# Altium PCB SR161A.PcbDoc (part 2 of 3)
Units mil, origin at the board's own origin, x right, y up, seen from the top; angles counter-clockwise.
Board outline 3150 x 3740 mil, 6 copper layers (Top Layer, Signal Layer 1, Signal Layer 2, Signal Layer 3, Signal Layer 4, Bottom Layer), stack 61.4 mil thick; 187 components, 70 nets, 452 pads, 384 vias.
Unrouted connection lines stored in the file: 5.
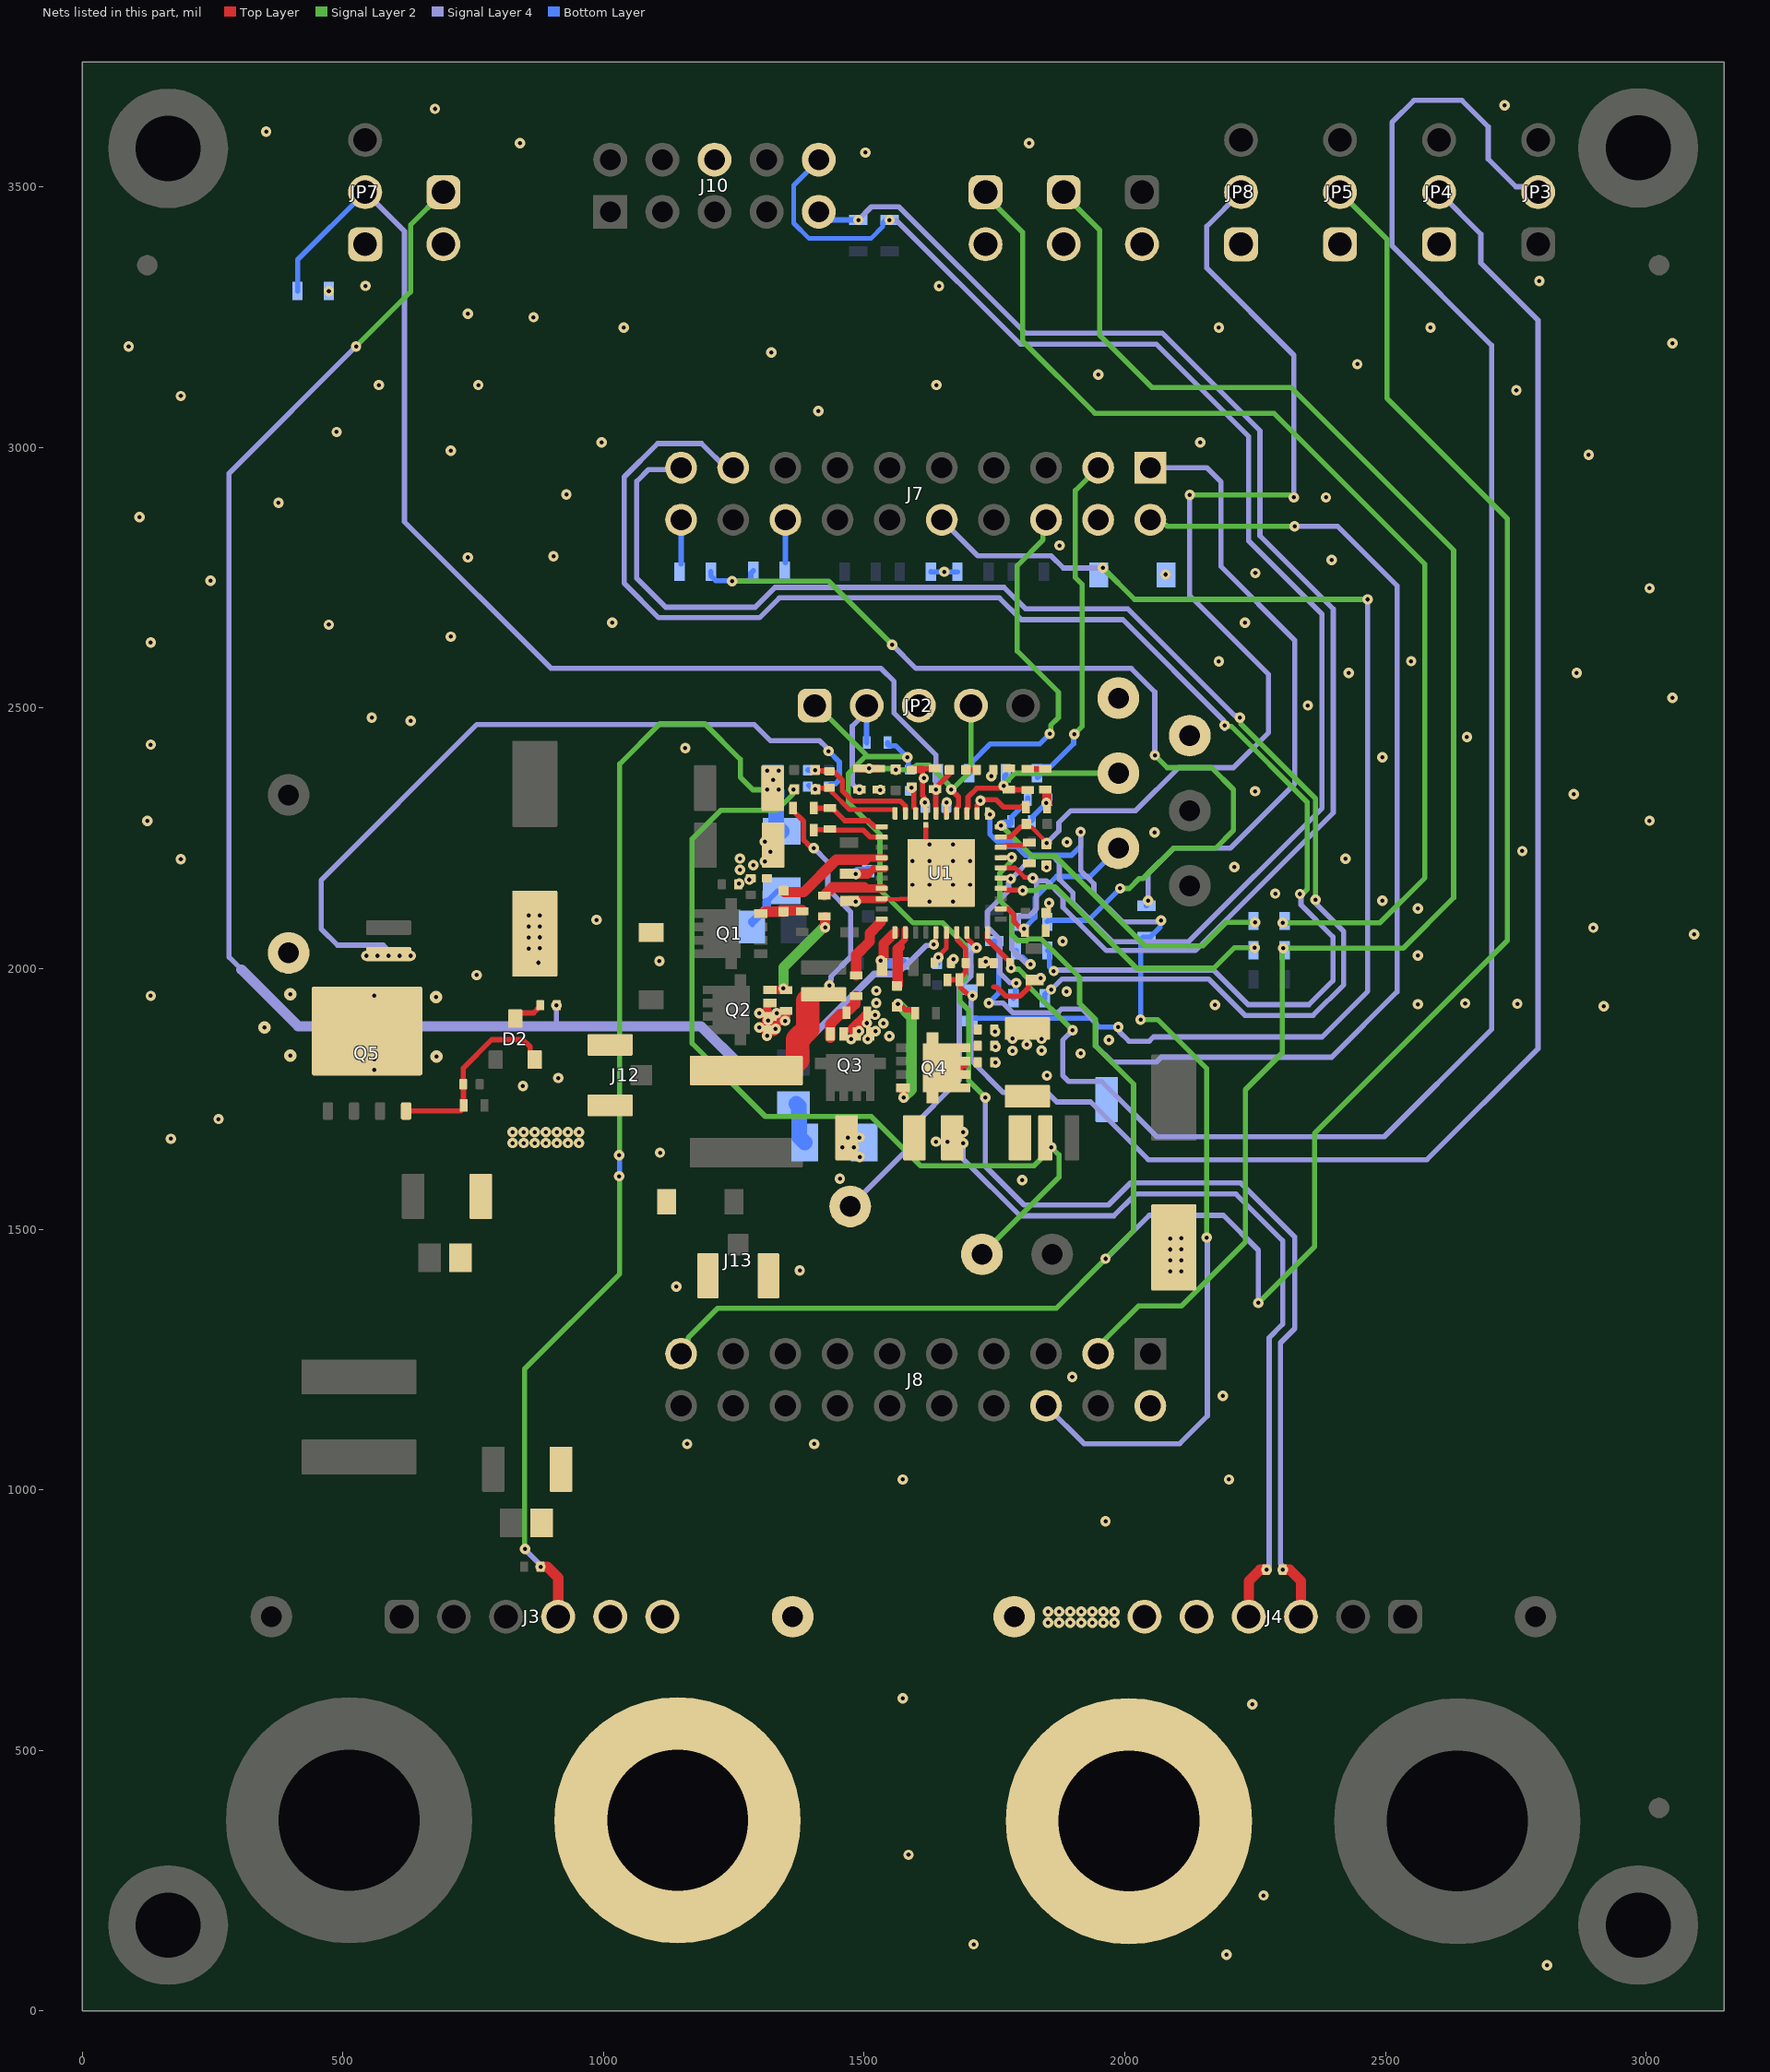
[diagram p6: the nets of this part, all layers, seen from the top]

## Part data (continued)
C35: library part CMP-0006478-2, "CAP, CERM, 56 pF, 50 V, +/- 5%, C0G/NP0, 0402", Cap_Case=0402, Manufacturer=MuRata, Supplier Part Number 1=14T3298, TempCo=C0G/NP0, Tolerance_%=5%, Value1=Unknown, Value2=50V, ValueDisplayed=56pF
C36: library part CMP-0006698-2, "CAP, CERM, 8200 pF, 50 V, +/- 10%, X7R, 0402", Cap_Case=0402, Manufacturer=MuRata, Supplier Part Number 1=GRM155R71H822KA88D-ND, TempCo=X7R, Tolerance_%=10%, Value1=Unknown, Value2=50V, ValueDisplayed=8200pF
C37: library part CMP-0006647-2, "CAP, CERM, 0.022 uF, 16 V, +/- 10%, X7R, 0402", Cap_Case=0402, Manufacturer=MuRata, Supplier Part Number 1=490-3256-1-ND, TempCo=X7R, Tolerance_%=10%, Value1=Unknown, Value2=16V, ValueDisplayed=0.022uF
C43 C45: library part CMP-0008374-2, "CAP, CERM, 0.47 uF, 100 V, +/- 10%, X7R, 0805", Cap_Case=0805, Manufacturer=MuRata, Supplier Part Number 1=490-3326-1-ND, TempCo=X7R, Tolerance_%=10%, Value1=Unknown, Value2=100V, ValueDisplayed=0.47uF
D1: library part CMP-0005781-3, "Diode, Zener, 3.3 V, 500 mW, SOD-123", Manufacturer="ON Semiconductor", Power_W=500mW, Value1=0.5W
D2: library part CMP-0096356-1, "Diode Array 1 Pair Series Connection Schottky 70 V 200mA (DC) Surface Mount TO-236-3, SC-59, SOT-23-3", Digikey Part Number=BAS70-04-E3-18GICT-ND, Forward Current=200mA, Manufacturer=Vishay, Max Surge Forward Current=600mA, Mouser Part Number=78-BAS70-04-E3-18, Operating Temperature Range="-55°C to +125°C", Peak Reverse Current=0.02uA, ValueDisplayed=1.5pF
D3 D6: library part CMP-0079239-2, "Diode, Schottky, 60 V, 1 A, AEC-Q101, SOD-123", Manufacturer=Nexperia, Value1=1A, Value2=0.66V
D4 D5: library part CMP-0077011-2, "Diode, Schottky, 60 V, 1 A, SOD-323F", Manufacturer=Nexperia, Value1=1A, Value2=0.66V
FID1 FID2 FID3 FID4 FID5 FID6: library part CMP-0077181-1, "Fiducial mark.  There is nothing to buy or mount.", Manufacturer=N/A
H1 H2 H3 H4: library part CMP-0003715-1, "MACHINE SCREW PAN PHILLIPS 4-40", Manufacturer="B&F Fastener Supply", Supplier Part Number 1=H703-ND
J1 J2 J5 J6: library part CMP-0055387-2, "Standard Banana Jack, Uninsulated, 15A", Manufacturer="Cinch Connectivity", Supplier Part Number 1=J147-ND
J3 J4: library part CMP-0054801-2, "Header, 2.54 mm, 6x1, Gold, TH", Color=Black, Manufacturer="Wurth Elektronik", Supplier Part Number 1=732-5319-ND
J7 J8: library part CMP-0079854-1, "Receptacle, 2.54mm, 10x2, Tin, TH", Color=Black, Current_A=6.3A, Manufacturer=Samtec, Supplier Part Number 1=SAM1204-10-ND, Voltage_V=550V
J9 J11 JP1 JP6: library part CMP-0054794-2, "Header, 2.54 mm, 2x1, Gold, TH", Color=Black, Manufacturer="Wurth Elektronik", Supplier Part Number 1=732-5315-ND
J10: library part CMP-0055448-2, "Header (shrouded), 100mil, 5x2, High-Temperature, Gold, TH", Manufacturer=3M, Supplier Part Number 1=MHC10K-ND
J12 J13: library part CMP-0124001-1, "U.FL (UMCC), I-PEX MHFI Connector Receptacle, Male Pin 50 Ohms Surface Mount Solder", Dielectric Material="Liquid Crystal Polymer", Digikey Part Number=SAM10680-ND, Frequency_Fixed=6GHz, Manufacturer=Samtec, Operating Temperature Range="-40°C to +90°C", Voltage_V=60V
JP2: library part CMP-0084909-1, "Header, 2.54mm, 5x1, Gold, TH", Color=Black, Current_A=3A, Manufacturer="Wurth Elektronik", Voltage_V=250V
JP3 JP4 JP5 JP7 JP8: library part CMP-0054796-4, "Header, 2.54 mm, 3x1, Gold, TH", Manufacturer="Wurth Elektronik", Supplier Part Number 1=732-5316-ND
L1: library part CMP-0127655-4, "3.3 µH Shielded Molded Inductor 20.4 A 6.5mOhm Max Nonstandard", Digikey Part Number=732-744393465033CT-ND, Manufacturer="Wurth Electronics", Mouser Part Number=710-744393465033, Operating Temperature Range="-55°C to +150°C", Self Resonant Frequency=21MHz, Test Frequency=100kHz, Tolerance_%=20%
L2: library part CMP-0126346-1, "2.2 µH Shielded Molded Inductor 12.4 A 9.3mOhm Max Nonstandard", Digikey Part Number=732-7443845030022CT-ND, Manufacturer="Wurth Electronics", Mouser Part Number=710-7443845030022, Operating Temperature Range="-40°C to +125°C", Self Resonant Frequency=35MHz, Test Frequency=100kHz, Tolerance_%=20%
Logo3: library part CMP-0074847-1, "FCC_disclaimer"
LOGO4: library part CMP-0074769-4, Manufacturer="Texas Instruments"
Logo5: library part CMP-0074837-2, "IEC 61010-1 Hot Surface Warning", Manufacturer="Texas Instruments"
Logo6: library part CMP-0074836-1, "IEC 61010-1 Caution Warning"
MP1 MP2 MP3 MP4: library part CMP-0090542-1, "Hex Standoff Threaded #4-40 Nylon 0.750\" (19.05mm) 3/4\" Natural", Digikey Part Number=36-1902D-ND, Manufacturer="Keystone Electronics", Mouser Part Number=534-1902D, Operating Temperature Range=to
NT3: library part CMP-0078142-6, "Single point connection between nets.", Manufacturer=N/A
Q1 Q2 Q3 Q4: library part CMP-0127418-3, "MOSFET N-Channel 40 V 72A (Tj) 45W (Tc) Surface Mount PG-TSDSON-8-44", Digikey Part Number=448-IAUZN04S7L046ATMA1CT-ND, Drain To Source Breakdown Voltage=40V, Input Capacitance At Vds="810pF @ 20V", Manufacturer=Infineon, Mouser Part Number=726-IAUZN04S7L046ATM, Operating Temperature Range="-55°C to +175°C", Power_W=45W, Pulse Drain Current=165A, Typ Forward Diode Voltage=0.8V
Q5: library part CMP-0000823-2, "MOSFET, N-CH, 60 V, 100 A, DNK0008A (VSON-CLIP-8)", Alternate Manufacturer=None, Manufacturer="Texas Instruments", Supplier Part Number 1=296-41076-1-ND, Value1=0.003, Value2="41 nC"
R1 R3: library part CMP-0097451-1, "10 mOhms ±1% 1W Chip Resistor Wide 0805 (2012 Metric), 0508 Automotive AEC-Q200, Current Sense Metal Foil", Manufacturer=Susumu, Operating Temperature Range="-55°C to +155°C", Power_W=1W, TempCo=50ppm/°C, Tolerance_%=1%
R2 R5 R7 R9 R10 R11 R13 R14 R15 R20 R24 R35 R36 R38 R52: library part CMP-0002710-1, "0 Ohms Jumper Chip Resistor 0402 (1005 Metric) Automotive AEC-Q200 Thick Film", Digikey Part Number=P0.0JCT-ND, Manufacturer=Panasonic, Mouser Part Number=667-ERJ-2GE0R00X, Operating Temperature Range="-55°C to +155°C", Power=100mW
R4: library part CMP-0095678-1, "4 mOhms ±1% 1W Chip Resistor Wide 0805 (2012 Metric), 0508 Automotive AEC-Q200, Current Sense Metal Foil", Digikey Part Number=408-1594-1-ND, Manufacturer=Susumu, Mouser Part Number=754-KRL2012EMR004FT5, Operating Temperature Range="-55°C to +155°C", Power_W=1W, TempCo=50ppm/°C, Tolerance_%=1%
R6 R16 R27 R33 R41 R42 R43 R49 R50 R51 R55: library part CMP-0023343-3, "RES, 0, 1%, 0.1 W, AEC-Q200 Grade 0, 0603", Manufacturer="Stackpole Electronics Inc", Power_W=100mW, Supplier Part Number 1=RMCF0603ZT0R00CT-ND, TempCo=ppm/C, Tolerance_%=1%, Value2=0.1W, Value_Code=0
R8 R17 R18: library part CMP-0025963-3, "RES, 10.0, 1%, 0.063 W, AEC-Q200 Grade 0, 0402", Manufacturer=Vishay-Dale, Power_W=63mW, Supplier Part Number 1=541-10.0LCT-ND, TempCo="100 ppm/C", Tolerance_%=1%, Value2=0.063W, Value_Code=10R0, ValueDisplayed=10.0
R12: library part CMP-0026744-1, "RES, 82.0 k, 1%, 0.063 W, 0402", Manufacturer="Yageo America", Power_W=63mW, Supplier Part Number 1=311-82.0KLRCT-ND, TempCo="100 ppm/C", Tolerance_%=1%, Value2=0.063W, Value_Code=82k0, ValueDisplayed=82.0k
R19: library part CMP-0026240-2, "RES, 2.67 k, 1%, 0.063 W, AEC-Q200 Grade 0, 0402", Manufacturer=Vishay-Dale, Power_W=63mW, Supplier Part Number 1=541-2.67KLCT-ND, TempCo="100 ppm/C", Tolerance_%=1%, Value2=0.063W, Value_Code=2k67, ValueDisplayed=2.67k
R21: library part CMP-0026543-2, "RES, 75.0 k, 1%, 0.063 W, AEC-Q200 Grade 0, 0402", Manufacturer=Vishay-Dale, Power_W=63mW, Supplier Part Number 1=541-75.0KLCT-ND, TempCo="100 ppm/C", Tolerance_%=1%, Value2=0.063W, Value_Code=75k0, ValueDisplayed=75.0k
R22: library part CMP-0025993-3, "RES, 12.7 k, 1%, 0.063 W, AEC-Q200 Grade 0, 0402", Manufacturer=Vishay-Dale, Power_W=63mW, Supplier Part Number 1=541-12.7KLCT-ND, TempCo="100 ppm/C", Tolerance_%=1%, Value2=0.063W, Value_Code=12k7, ValueDisplayed=12.7k
R23 R26: library part CMP-0018676-3, "RES, 3.0, 5%, 0.25 W, AEC-Q200 Grade 0, 1206", Manufacturer=Vishay-Dale, Power_W=250mW, Supplier Part Number 1=541-3.0ECT-ND, TempCo="200 ppm/C", Tolerance_%=5%, Value2=0.25W, Value_Code=3R00, ValueDisplayed=3.0
R25: library part CMP-0077124-1, "RES, 10.0 k, 0.1%, 0.1 W, AEC-Q200 Grade 0, 0402", Manufacturer=Vishay/Beyschlag, Power_W=100mW, Supplier Part Number 1=MCS0402-10.0K-MBCT-ND, TempCo="25 ppm/C", Tolerance_%=0.1%, Value2=0.1W, Value_Code=10k0, ValueDisplayed=10.0k
R28 R32: library part CMP-0026925-3, "RES, 3.0, 5%, 0.063 W, AEC-Q200 Grade 0, 0402", Manufacturer=Vishay-Dale, Power_W=63mW, Supplier Part Number 1=541-3.0JCT-ND, TempCo="200 ppm/C", Tolerance_%=5%, Value2=0.063W, Value_Code=3R00, ValueDisplayed=3.0
R29: library part CMP-0026591-2, "RES, 8.66 k, 1%, 0.063 W, AEC-Q200 Grade 0, 0402", Manufacturer=Vishay-Dale, Power_W=63mW, Supplier Part Number 1=541-8.66KLCT-ND, TempCo="100 ppm/C", Tolerance_%=1%, Value2=0.063W, Value_Code=8k66, ValueDisplayed=8.66k
R30: library part CMP-0026367-2, "RES, 40.2 k, 1%, 0.063 W, AEC-Q200 Grade 0, 0402", Manufacturer=Vishay-Dale, Power_W=63mW, Supplier Part Number 1=541-40.2KLCT-ND, TempCo="100 ppm/C", Tolerance_%=1%, Value2=0.063W, Value_Code=40k2, ValueDisplayed=40.2k
R31: library part CMP-0026028-3, "RES, 15.4 k, 1%, 0.063 W, AEC-Q200 Grade 0, 0402", Manufacturer=Vishay-Dale, Power_W=63mW, Supplier Part Number 1=541-15.4KLCT-ND, TempCo="100 ppm/C", Tolerance_%=1%, Value2=0.063W, Value_Code=15k4, ValueDisplayed=15.4k
R34: library part CMP-0026463-2, "RES, 5.11 k, 1%, 0.063 W, AEC-Q200 Grade 0, 0402", Manufacturer=Vishay-Dale, Power_W=63mW, Supplier Part Number 1=541-5.11KLCT-ND, TempCo="100 ppm/C", Tolerance_%=1%, Value2=0.063W, Value_Code=5k11, ValueDisplayed=5.11k
R37: library part CMP-0026241-2, "RES, 2.74 k, 1%, 0.063 W, AEC-Q200 Grade 0, 0402", Manufacturer=Vishay-Dale, Power_W=63mW, Supplier Part Number 1=541-2.74KLCT-ND, TempCo="100 ppm/C", Tolerance_%=1%, Value2=0.063W, Value_Code=2k74, ValueDisplayed=2.74k
R39 R40 R44: library part CMP-0023000-5, "RES, 2.00 k, 1%, 0.1 W, 0603", Manufacturer=Yageo, Power_W=100mW, Supplier Part Number 1=311-2.00KHRCT-ND, TempCo="100 ppm/C", Tolerance_%=1%, Value2=0.1W, Value_Code=2k00, ValueDisplayed=2.00k
R45 R46: library part CMP-0023259-5, "RES, 71.5 k, 1%, 0.1 W, 0603", Manufacturer=Yageo, Power_W=100mW, Supplier Part Number 1=311-71.5KHRCT-ND, TempCo="100 ppm/C", Tolerance_%=1%, Value2=0.1W, Value_Code=71k5, ValueDisplayed=71.5k
R47 R48: library part CMP-0023153-5, "RES, 4.70 k, 1%, 0.1 W, 0603", Manufacturer=Yageo, Power_W=100mW, Supplier Part Number 1=311-4.70KHRCT-ND, TempCo="100 ppm/C", Tolerance_%=1%, Value2=0.1W, Value_Code=4k70, ValueDisplayed=4.70k
R53: library part CMP-0022852-5, "RES, 18.0 k, 1%, 0.1 W, 0603", Manufacturer=Yageo, Power_W=100mW, Supplier Part Number 1=311-18.0KHRCT-ND, TempCo="100 ppm/C", Tolerance_%=1%, Value2=0.1W, Value_Code=18k0, ValueDisplayed=18.0k
R54: library part CMP-0023653-3, "RES, 10.0 k, 0.1%, 0.1 W, 0603", Manufacturer="Yageo America", Power_W=100mW, TempCo="25 ppm/C", Tolerance_%=0.1%, Value2=0.1W, Value_Code=10k0, ValueDisplayed=10.0k
SH-JP1 SH-JP2 SH-JP3 SH-JP4 SH-JP5 SH-JP6 SH-JP7 SH-JP8: library part CMP-0078738-1, "Single Operation 2.54mm Pitch Open Top Jumper Socket", Manufacturer=Harwin, Supplier Part Number 1=952-2881-ND
TP1 TP2 TP5 TP6: library part CMP-0055140-2, "Test Point, Miniature, Orange, TH", Color=Orange, Manufacturer="Keystone Electronics", Supplier Part Number 1=36-5003-ND
TP3 TP14: library part CMP-0055137-2, "Test Point, Miniature, Red, TH", Color=Red, Manufacturer="Keystone Electronics", Supplier Part Number 1=36-5000-ND
TP4 TP7 TP8 TP15: library part CMP-0055138-2, "Test Point, Miniature, Black, TH", Color=Black, Manufacturer="Keystone Electronics", Supplier Part Number 1=36-5001-ND
TP9 TP10 TP11 TP12 TP13: library part CMP-0055141-2, "Test Point, Miniature, Yellow, TH", Color=Yellow, Manufacturer="Keystone Electronics", Supplier Part Number 1=36-5004-ND
U1: library part CMP-0127273-1, "36V VIN4 Switch Buck-Boost Controller with I2C", Manufacturer="Texas Instruments", Max Supply Voltage=36V, Min Supply Voltage=3.5V, Nominal Supply Current=65uA, Operating Temperature Range="-40°C to +150°C", Switching Frequency=100-2200kHz
ZZ2: library part CMP-0077236-1
ZZ3: library part CMP-0077237-1
ZZ4: library part CMP-0077238-1
ZZ5 ZZ6 ZZ7 ZZ8 ZZ9 ZZ10 ZZ11: library part CMP-0077238-1, "These assemblies must comply with workmanship standards IPC-A-610 Class 2, unless otherwise specified."

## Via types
v1: diameter 20, hole 8, Top Layer to Bottom Layer, tented both sides, 366 vias
v2: diameter 19.68, hole 7.87, Top Layer to Bottom Layer, tented both sides, 12 vias
v3: diameter 24, hole 8, Top Layer to Bottom Layer, tented both sides, 6 vias

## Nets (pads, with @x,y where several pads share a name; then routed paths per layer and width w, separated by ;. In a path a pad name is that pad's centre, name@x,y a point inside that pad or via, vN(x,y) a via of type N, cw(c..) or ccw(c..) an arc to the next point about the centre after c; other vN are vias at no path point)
3V3: J7.1 R54.2 | length 1200.7
  Signal Layer 4 w10: v1(2044.9,2130.65) 2044.9,2182.7 2093.48,2231.28 2202.29,2231.28 2326.15,2355.15 2326.15,2630.29 2184.7,2771.74 2184.7,2934 2157.28,2961.43 J7.1@2049.03,2961.43
  Bottom Layer w10: R54.2@2041.62,2120.99 2041.62,2121.2 2041.04,2121.78 2041.39,2122.14 2041.39,2127.15 v1(2044.9,2130.65)
5V0: J7.2 R49.2 | length 2354.3
  Signal Layer 2 w10: J7.2@2049.03,2861.43 2058.8,2851.66 2078.69,2851.66 2081.65,2848.7 v1(2325.79,2848.7)
  Signal Layer 4 w10: v1(1739.25,1934.23) 1766.66,1934.23 1785.27,1915.62 1871.43,1915.62 1878.26,1922.45 1918.6,1922.45 1944.32,1896.73 1944.32,1852.62 1975.7,1821.23 2061.2,1821.23 2070.19,1830.22 2396.78,1830.22 2522.2,1955.63 2522.2,2735.1 2408.59,2848.7 v1(2325.79,2848.7)
  Bottom Layer w10: v1(1739.25,1934.23) 1757.96,1952.93 1757.96,2048.15 1752.57,2053.54 R49.2@1749.42,2053.54
ADDR: JP8.2 R36.2 R38.1 U1.9 | length 2043.5
  Top Layer w8: R36.2@1811.28,2271.06 1821.87,2271.06 1843.62,2249.3 1843.62,2244.14 1844.47,2243.29 1848.53,2243.29 R38.1@1848.53,2239.23
  Top Layer w10: U1.9@1762.17,2252.65 1768.91,2252.65 1768.98,2252.73 1780.82,2252.73 1800.16,2272.06 R36.2@1812.32,2272.06 ; R38.1@1848.53,2239.23 1850.14,2239.23 R38.1@1850.14,2236.56
  Signal Layer 2 w10: v1(2124.72,2909.37) 2316.73,2909.37 2321.73,2904.37 v1(2324.44,2904.37)
  Signal Layer 4 w10: v1(1850.6,2241.56) 1873.73,2264.74 1873.73,2280.39 1896.63,2303.28 2021.03,2303.28 2103.54,2385.79 2208.58,2385.79 2275.85,2453.05 2275.85,2564.69 2124.72,2715.82 v1(2124.72,2909.37) ; JP8.2@2223,3490.37 2157.28,3424.65 2157.28,3344.26 2324.44,3177.1 v1(2324.44,2904.37)
AGND: C14.2 C15.1 C16.2 C18.2 C26.1 C28.1 C29.2 C34.2 C35.2 C36.2 C37.2 D1.2 J9.2 J10.6 J11.2 JP1.2 JP2.3 JP4.1 JP5.1 JP6.2 JP7.1 JP8.1 NT3.2 R10.1 R19.1 R22.1 R24.2 R30.1 R31.1 R37.1 R38.2 R47.1 R48.1 R53.1 TP4.1 TP7.1 U1.17 | length 379.4
  Top Layer w10: C16.2@1591.32,2381.25 C16.2@1592.05,2381.98 ; 1611.78,2381.98 1612.51,2382.71 ; v1@1616.4,2319.5 1614.48,2321.41 1614.48,2329.97 1612.51,2331.95 1612.51,2365.61 1612.51,2382.71 ; v1@1618.39,2316.21 1618.39,2303.83 1618.47,2303.76 U1.17@1618.47,2297.93 ; C14.2@1635.97,2384.45 1635.11,2383.58 1613.38,2383.58 1612.51,2382.71 ; C29.2@1724.64,2009.23 1725.08,2009.66 1733.24,2009.66 v1(1733.24,2013.72) C29.2@1733.3,2013.78 ; C28.1@1748.82,2013.78 C28.1@1748.87,2013.83 ; 1749,1965.18 1753.03,1965.18 1754.86,1963.35 1756.02,1963.35 1771.82,1947.55 1799.37,1947.55 1814.66,1962.84 1814.66,1973.7 1822.74,1981.77 C26.1@1838.46,1981.77
  Top Layer w14: C16.2@1592.05,2381.98 1611.78,2381.98
  Top Layer w18: C36.2@1850.6,2341.95 1850.6,2320.47 R31.1@1852.32,2318.75
  Bottom Layer w10: R48.1@1628.34,2761.76 1628.45,2761.65 R47.1@1678.93,2761.65 ; C35.2@1822.02,2285.09 1823.72,2286.8 1823.72,2292.18 v1(1849.63,2318.09) ; R30.1@1850.91,2318.86 R30.1@1851.64,2318.13
  other v1: 2810,88.08 2194.94,108.08 1573.91,600 1573.91,1020 2188.02,1180.43 1899.26,1216.68 1139.75,1390.05 1803.18,1594.72 261.74,1711.72 845.65,1775 1850.76,1794.99 1915.27,1837.45 1969.54,1863.66 2919.05,1928.02 2173,1930.68 2562.06,1931.92 2753,1932.86 2653,1933.62 1888.55,1956.44 1838.51,1982.02 1671.33,2018.06 2562.56,2025.37 1880.81,2052.64 3092.45,2066.21 2898.81,2078.71 2562.06,2115.59 1855.01,2126.43 2494.04,2130.62 2288.59,2144.22 1849.78,2194.71 2210.16,2195.24 2423.39,2211.07 2762.58,2225.79 1889.33,2243.24 2057.36,2261.62 125,2283.54 3006.79,2283.98 1616.22,2318.96 2861.33,2334.81 2250.22,2340.6 1531.16,2343.24 1614.51,2365.61 1743.97,2369.34 2494.04,2405.59 1156.96,2423.68 2656.45,2444.77 630.48,2475.53 2351.24,2505.1 3050.51,2520 2429.4,2567.39 2866.95,2567.39 2180.52,2590 2549.43,2590.12 131.66,2625.86 707.24,2637.18 473.23,2660.18 1016.71,2664.16 2230.82,2664.18 3006.79,2730 246.43,2744.78 2078.37,2756.51 2250.46,2759.19 1653.69,2761.65 2396.78,2784.25 740,2789.26 904.19,2791.35 1874.71,2812.21 110,2866.76 376.79,2893.84 2385.99,2904.37 928.95,2910 2890,2986.3 707.24,2993.84 996.6,3010 2144.72,3010 488.21,3030 1412.06,3070 189.28,3098.97 2751.2,3110 569.08,3120 760,3120 1638.99,3120 1949.03,3140 2446.1,3160 1322.17,3182.55 89.29,3193.88 3050.51,3200 1039.08,3230 2180.52,3230 2586.6,3230 865.96,3250 740,3256.68 473.23,3300 543.61,3310.24 1643.7,3309.63 2795.25,3319.69 1502.51,3566.01 840,3583.84 1816.62,3583.84 353,3606.4 676.76,3650 2728.43,3656.8
BIAS: C28.2 JP3.2 U1.40 | length 3525.9
  Top Layer w10: U1.40@1736.58,2069.58 1736.58,2056.35 1777.26,2015.67 1777.49,2015.67 1778.49,2014.68 C28.2@1778.49,2014.45
  Signal Layer 2 w10: v1(1781.76,2001.17) 1783.68,1999.25 1796.54,1999.25 1814.55,1981.24 1814.55,1967.41 v1(1899.99,1881.97)
  Signal Layer 4 w10: v1(1899.99,1881.97) 1880.88,1862.86 1880.88,1795.3 1892.63,1783.55 1955.91,1783.55 2061.78,1677.68 2497.68,1677.68 2703.62,1883.62 2703.62,3196.38 2512.78,3387.22 2512.78,3624.05 2554.81,3666.07 2646.7,3666.07 2697.13,3615.64 2697.13,3553.62 2750.24,3500.52 2782.85,3500.52 JP3.2@2793,3490.37
CDC: C35.1 R30.2 R50.1 U1.10 | length 688.2
  Top Layer w10: U1.10@1762.17,2272.34 1768,2272.34 1768.08,2272.42 U1.10@1768.08,2276.26
  Signal Layer 2 w10: v1@1763.44,2274.65 1822.39,2215.71 1866.94,2215.71 2038.75,2043.89 2149.79,2043.89 2194.91,2089.01 v1(2250.16,2089.01)
  Bottom Layer w10: v1(1762.9,2274.65) 1765.61,2274.65 v1@1769.9,2278.94 ; C35.1@1779.52,2278.94 1782.02,2281.44 C35.1@1782.02,2285.09 ; C35.1@1782.02,2290.44 1783.66,2290.44 1783.72,2290.5 1783.72,2292.15 1811.1,2319.53 1811.51,2319.53 1813.99,2322.01 R30.2@1813.99,2327.9
  Bottom Layer w15: v1@1769.9,2278.94 C35.1@1779.52,2278.94
CDCP: J11.1 R50.2 | length 2172.3
  Signal Layer 2 w10: J11.1@1730.52,3486.8 1803.91,3413.41 1803.91,3204.54 1942.55,3065.89 2286.11,3065.89 2575.79,2776.21 2575.79,2174.35 2489.85,2088.41 v1(2302.86,2088.41)
CFG2: R37.2 U1.8 | length 51.7
  Top Layer w10: U1.8@1768.98,2233.05 1772.67,2236.73 1807.28,2236.73 1812.5,2241.96 R37.2@1817,2241.96
COMP: C34.1 R16.2 R29.2 TP12.1 U1.13 | length 410.1
  Top Layer w10: U1.13@1697.21,2297.93 1697.21,2306.55 1699.42,2308.76 1699.42,2329.67 1715.95,2346.2 1760.38,2346.2 1764.92,2350.74 v1(1767.62,2350.74) 1767.62,2349.94 1773.44,2344.12 C34.1@1777.94,2344.12 ; C34.1@1782.49,2343.28 R29.2@1813.66,2343.28
  Signal Layer 2 w10: v1(1767.62,2350.74) 1767.62,2353.44 1782.21,2368.03 1782.21,2368.21 1789.28,2375.28 TP12.1@1987.84,2375.28
  Bottom Layer w10: v1(1767.62,2350.74) 1769.54,2352.65 1769.54,2369.49 R16.2@1772.51,2372.46
CSA/SW1: C25.2 R17.1 U1.22 | length 139.4
  Top Layer w10: R17.1@1403.57,2260.5 1410.09,2267.03 C25.2@1434.66,2267.03 ; C25.2@1434.64,2268.19 1436.96,2265.87 1498.63,2265.87 1511.85,2252.65 U1.22@1533.83,2252.65
CSB: C25.1 R18.1 U1.21 | length 137.4
  Top Layer w10: R18.1@1403.53,2307.9 C25.1@1434.35,2307.9 ; C25.1@1441.39,2305.94 1441.64,2305.69 1441.64,2305.25 1462.89,2284 1508.48,2284 1520.14,2272.34 U1.21@1533.83,2272.34
DRV1: C6.1 J9.1 U1.35 | length 3237.2
  Top Layer w9: v1(1633.81,2046.6) 1633.81,2049.58 1637.74,2053.5 1637.74,2069.16 U1.35@1638.16,2069.58
  Signal Layer 2 w10: v1@525.54,3194.25 630,3298.71 630,3427.37 J9.1@693,3490.37
  Signal Layer 4 w10: 305.81,1998.43 281.93,2022.31 281.93,2950.64 v1@525.54,3194.25 ; 909.19,1889.65 909.85,1890.3 v1(909.85,1929.76) ; 1564.27,1989.85 1619.31,2044.9 1632.11,2044.9 v1(1633.81,2046.6)
  Signal Layer 4 w13: 1344.36,1814.95 1519.26,1989.85 1564.27,1989.85
  Signal Layer 4 w20: 305.81,1998.43 414.6,1889.65 909.19,1889.65 1187.21,1889.65 1261.9,1814.95 1344.36,1814.95
  other v1: 525.54,3193.88
DTRK: R51.1 U1.4 | length 565.6
  Top Layer w10: U1.4@1768.98,2154.15 1771.89,2151.24 1803.67,2151.24 v1(1804.57,2150.34)
  Signal Layer 2 w10: v1(1804.57,2150.34) 1831.03,2150.34 1838,2157.31 1866.62,2157.31 2022.78,2001.14 2171,2001.14 2210.06,2040.2 v1(2249.26,2040.2)
DTRKP: J8.3 JP1.1 R51.2 | length 3158.2
  Signal Layer 2 w10: JP1.1@1882.18,3486.8 1951.87,3417.11 1951.87,3215.52 2051.99,3115.39 2318.61,3115.39 2630.78,2803.22 2630.78,2136.12 2534.26,2039.6 v1(2304.06,2039.6) 2302.34,2037.88 2302.34,1838.7 2231.56,1767.92 2231.56,1475.79 2108.85,1353.09 2026.37,1353.09 1964.05,1290.77 1964.05,1290.25 1949.03,1275.23 J8.3@1949.03,1260.42
EN/UVLO: C29.1 JP4.2 R21.1 R22.2 R44.1 U1.37 | length 3251.2
  Top Layer w9: U1.37@1677.53,2069.58 1677.95,2069.16 1677.95,2055.71 1695.06,2038.6 C29.1@1695.06,2011.25
  Top Layer w10: R21.1@1660.03,1978.74 1660.14,1978.86 1680.49,1978.86 1680.6,1978.97 R22.2@1682.99,1978.97 ; R22.2@1685.49,1979.47 1685.49,1964.03 1696.67,1952.85 ; R22.2@1687.54,1986.55 1694.76,1993.77 C29.1@1694.76,2013.59
  Signal Layer 4 w10: v1(1708.08,1948.19) 1706.17,1946.27 1706.17,1939.2 1705.25,1938.29 1705.25,1824.09 1766.64,1762.69 1851.42,1762.69 1869.73,1744.39 1934.52,1744.39 2045.29,1633.62 2579.53,1633.62 2792.69,1846.77 2792.69,3244.35 2683,3354.04 2683,3409.56 JP4.2@2603,3489.56
EN/UVLOP: D1.1 J7.10 R44.2 | length 2452
  Signal Layer 2 w10: v1(1957.98,2769.35) 2018.61,2708.72 v1(2466.1,2708.72)
  Signal Layer 4 w10: J7.10@1649.03,2861.43 1649.03,2849.95 1660.51,2849.95 1718.08,2792.38 1858.78,2792.38 1882.21,2768.95 v1@1950.55,2768.95 ; v1@1989.75,1879.42 2008.1,1861.08 2046.96,1861.08 2055.12,1869.24 2378.59,1869.24 2466.1,1956.75 v1(2466.1,2708.72)
  Bottom Layer w10: R44.2@1700,1900 1705,1905 1934.86,1905 1951.78,1888.08 v1(1987.57,1888.08)
FB: JP2.4 R2.1 R12.1 R19.2 U1.14 | length 450.5
  Top Layer w10: v1(1666.83,2344.04) 1681.12,2329.75 1681.12,2311.61 1677.54,2308.03 U1.14@1677.53,2297.93
  Top Layer w15: R12.1@1491.02,2384.12 v1(1509.69,2384.11) ; v1(1509.69,2384.11) R19.2@1528.4,2384.07
  Signal Layer 2 w10: v1@1510.89,2384.06 v1@1560.86,2384.06 ; v1@1560.78,2383.24 1560.86,2383.17 v1(1560.86,2381.68) ; v1@1562.34,2381.68 1592.35,2381.68 1601.14,2390.48 1624.91,2390.48 1661.83,2353.55 1661.83,2351.75 1666.83,2346.75 v1(1666.83,2344.04) 1669.14,2344.04 1705,2379.91 JP2.4@1705,2505
GND: C1.1 C3.1 C5.1 C7.1 C8.1 C9.1 C10.1 C11.2 C12.2 C13.1 C17.1 C19.1 C20.1 C21.1 C23.2 C24.1 C27.1 C39.2 C40.1 C41.2 C42.2 C43.2 C44.1 C45.2 D3.2 D6.2 J3.4 J3.5 J3.6 J4.4 J4.5 J4.6 J5.1 J6.1 J7.4 J8.2 J12.2 J12.3 J13.2 J13.3 NT3.1 Q2.1 Q2.2 Q2.3 Q3.1 Q3.2 Q3.3 R23.2 R26.2 TP8.1 TP15.1 U1.28 U1.41 | length 4140.4
  Top Layer w9: U1.28@1536.96,2133.1 U1.41@1598.5,2134.26
  Top Layer w10: Q2.2@1316.89,1911.11 Q2.3@1316.89,1930.47 ; NT3.1@1618.3,2274.71 1618.3,2243.72 1623.14,2238.87 v2(1625.36,2238.87)
  Top Layer w14: C27.1@1471.87,2130.07 1474.9,2133.1 1536.96,2133.1 U1.28@1538.59,2133.1
  Top Layer w20: v1(879.42,852.61) 892.13,852.61 913.61,831.13 J3.4@913.61,756.82 ; v1@1313.58,1871.61 1313.58,1918.86 ; Q2.1@1317.97,1882.81 Q2.1@1319.23,1882.81 ; Q2.2@1319.23,1908.4 1320.38,1909.54 1344.87,1909.54 ; v1(1330.42,1884.65) 1326.88,1881.1 1320.94,1881.1 Q2.1@1319.23,1882.81 ; 1333.56,1897.13 Q2.1@1319.23,1882.81 ; C27.1@1471.87,2130.07 C27.1@1478.3,2130.07 ; 1477.66,1883.92 C23.2@1503.66,1909.93 ; J4.4@2238,751.05 J4.4@2238,756.82 2238,825.37 2259.48,846.85 v1(2272.19,846.85) ; 1344.87,1909.54 1348.84,1909.54 1348.84,1913.51 1344.87,1909.54
  Signal Layer 2 w10: v1(849.71,886.98) 848.82,887.87 848.82,1232.28 1031.24,1414.7 v1@1031.24,1601.97 ; v1@1031.24,1642.19 1031.24,2393.07 1107.97,2469.8 1194.75,2469.8 1262.53,2402.01 1262.53,2367.69 1286.73,2343.49 v1(1314.45,2343.49)
  Signal Layer 4 w10: v1(849.71,886.98) 849.71,885.25 874.42,860.54 874.42,860.32 879.42,855.32 v1(879.42,852.61) ; v1@1691.53,1664.26 1690.13,1662.86 1690.13,1634.9 1799.13,1525.9 1979.07,1525.9 2021.02,1567.85 2213.21,1567.85 2302.86,1478.2 2302.86,1317.96 2277,1292.1 2277,854.36 2272.19,849.55 v1(2272.19,846.85)
  Bottom Layer w10: v1@1031.24,1601.97 v1@1031.24,1642.19 ; v1(1638.05,1668.23) v1(1659.63,1668.23) 1684.36,1668.23 1687.42,1665.17 v1(1690.13,1665.17)
  Bottom Layer w30: C19.1@1325.01,2333.95 1331.66,2327.3 1331.66,2273.96 R23.2@1342.15,2263.48 ; C19.1@1325.01,2347.5 1331.9,2340.61 C19.1@1331.9,2332.03
  other v1: 1710,128.08 2266.27,221.92 1585.24,300 2244.6,588.67 1852.59,745.52 1873.86,745.52 1895.12,745.52 1916.38,745.52 1937.65,745.52 1958.91,745.52 1980.17,745.52 1852.59,766.63 1873.86,766.63 1895.12,766.63 1916.38,766.63 1937.65,766.63 1958.91,766.63 1980.17,766.63 1963.04,940 2199.9,1020 1160.58,1088.18 1404.32,1088.18 2087.13,1419.03 2108.14,1419.73 1376.56,1421.4 2087.13,1440.22 2108.14,1440.92 2087.13,1461.41 2108.14,1462.12 2087.13,1482.6 2108.14,1483.31 1453.54,1596.97 1030,1601.97 1491.62,1638.78 1030,1642.19 1108.52,1647.02 1458.02,1657.54 1480.35,1657.54 825.65,1665.64 846.91,1665.64 868.17,1665.64 889.44,1665.64 910.7,1665.64 931.97,1665.64 953.23,1665.64 170,1673.81 1469.08,1676.3 1491.41,1676.3 825.65,1686.75 846.91,1686.75 868.17,1686.75 889.44,1686.75 910.7,1686.75 931.97,1686.75 953.23,1686.75 1690.13,1686.75 913.17,1790.44 1751.91,1819.75 1784.56,1842.64 1840.28,1843.17 1752.4,1850 1812.4,1854.42 1475.02,1864.97 1507.07,1864.97 1784.56,1866.23 1840.45,1865.54 1313.78,1871.12 1548.77,1870.51 1490.31,1880.36 1522.15,1880.05 1751.39,1879.52 1299.1,1887.48 1537.2,1895.48 1505.59,1895.76 1348.84,1900.1 1315.74,1901.01 1521.26,1911.66 1299.1,1914.54 1332.38,1914.54 1523.44,1934.23 131.66,1948.04 1523.44,1957.75 756.55,1987.93 874.89,2011.65 1107.45,2014.68 856.89,2038.41 877.9,2039.12 856.89,2059.61 877.9,2060.31 856.89,2080.8 877.9,2081.51 986.85,2093.78 856.89,2101.99 877.9,2102.7 1484.07,2128.88 1260.5,2163.16 1279.9,2170.9 1261.91,2189.64 1287.59,2198.68 1309.3,2206.18 189.28,2210 1262.11,2211.45 1320.24,2224.79 1309.6,2244.09 1336.26,2343.49 1325.55,2362.04 1314.21,2379.68 1336.02,2379.68 131.66,2430 555.54,2481.91
  other v2: 1625.36,2128.64 1670.64,2128.64 1592.88,2161.12 1625.36,2161.12 1670.64,2161.12 1703.12,2161.12 1592.88,2206.39 1625.36,2206.39 1670.64,2206.39 1703.12,2206.39 1670.64,2238.87
HB1: C31.2 D4.1 U1.25 | length 80.3
  Top Layer w14: 1511.11,2185.17 1517.78,2191.83 U1.25@1539.78,2191.83
  Top Layer w20: C31.2@1482.8,2182.42 1506.13,2182.42
  Bottom Layer w20: v1(1484.31,2182.14) 1487.57,2185.4 1505.9,2185.4 D4.1@1507.71,2187.21
HB2: C33.2 D5.1 U1.31 | length 117.4
  Top Layer w12: U1.31@1560.28,2063.52 U1.31@1560.28,2075.52
  Top Layer w20: C33.2@1531.87,2015.39 1537.44,2020.96 1537.44,2047.6 U1.31@1556.34,2066.5
  Bottom Layer w20: v1(1532.12,2015.64) 1537.64,2010.13 D5.1@1573.96,2010.13
HO1: R13.2 U1.24 | length 216
  Top Layer w10: U1.24@1533.75,2213.36 U1.24@1533.83,2213.28
  Top Layer w14: 1504.57,2212.17 U1.24@1539.57,2212.17
  Top Layer w20: R13.2@1347.59,2147.16 1356.98,2147.16 1384.55,2147.15 1446.7,2209.31 1502.73,2209.31
HO1_G: C38.1 Q1.4 R13.1 | length 82.7
  Top Layer w20: Q1.4@1304.69,2106.87 1307.96,2106.87 1310.75,2109.66 R13.1@1345.59,2109.66 ; R13.1@1340.53,2112.23 C38.1@1381.16,2112.23
HO2: R20.2 U1.32 | length 113
  Top Layer w12: 1568.38,2041.77 1568.38,2045.99 1576.34,2053.95 1576.34,2054.24 1578.34,2056.24 U1.32@1578.34,2075.74
  Top Layer w20: R20.2@1564.3,1968.52 1564.3,2037.69 1568.38,2041.77
HO2_G: C22.2 Q4.4 R20.1 | length 255.9
  Top Layer w10: v1(1564.88,1932.76) 1567.58,1932.76 1571.44,1928.91 1578.8,1921.54 1592.55,1921.54 1595.05,1919.04 C22.2@1595.05,1914.54 ; Q4.4@1574.66,1771.35 Q4.4@1575.41,1770.6 ; v1@1575.41,1753.83 v1(1576.16,1753.08)
  Top Layer w16: v1@1575.41,1753.83 Q4.4@1575.41,1770.6
  Signal Layer 2 w20: v1(1564.88,1932.76) 1590.98,1906.65 1590.98,1767.91 v1(1576.16,1753.08)
ILIMCOMP: C14.1 JP7.2 R52.2 R53.2 R55.1 U1.16 | length 2328.1
  Top Layer w10: 1637.45,2312.67 C14.1@1637.45,2339.03 ; 1637.48,2312.63 1637.48,2309.97 1638.16,2309.29 U1.16@1638.16,2297.93 ; C14.1@1639.63,2349.51 R52.2@1665.85,2375.73
  Signal Layer 4 w10: JP7.2@543,3490.37 618.29,3415.08 618.29,2857.63 899.48,2576.44 1532.23,2576.44 1557.49,2551.18 1557.49,2490.46 1638.08,2409.88 v1(1638.08,2344.02)
  Bottom Layer w10: R53.2@413.23,3300.37 413.23,3360.23 JP7.2@543,3490 ; R55.1@1637.32,2377.85 1639.91,2375.26 1638.99,2374.34 1638.99,2344.94 v1(1638.08,2344.02)
ISNSN: C2.1 R11.1 R15.1 U1.19 | length 236.1
  Top Layer w10: v1(1405.98,2381.4) 1407.7,2379.68 C2.1@1432.72,2379.68 ; C2.1@1433.47,2378.93 C2.1@1432.72,2379.68 ; U1.19@1579.02,2304.74 1579.02,2312.43 1570.03,2321.43 1478.45,2321.43 1458.39,2341.48 1458.39,2361.71 1444.05,2376.05 1436.35,2376.05 C2.1@1432.72,2379.68
  Bottom Layer w10: R11.1@1392.24,2381.4 1392.44,2381.2 1405.78,2381.2 v1(1405.98,2381.4)
ISNSP: C2.2 R5.1 R14.1 U1.20 | length 194.5
  Top Layer w9: C2.2@1437.82,2345.05 1438.82,2344.06 1438.82,2338.5 1472.17,2305.14 1559,2305.14 1559.42,2304.72 U1.20@1559.42,2297.93
  Top Layer w10: v1(1406.4,2344.6) 1408.02,2346.21 1432.26,2346.21 C2.2@1433.47,2347.43 ; R14.1@1409.1,2344.41 R14.1@1409.1,2345.05
  Bottom Layer w10: R5.1@1394.11,2351.75 v1@1406.31,2339.56
LO1: R28.1 U1.27 | length 121.3
  Top Layer w16: 1499.82,2156.1 1501.7,2154.23 U1.27@1537.7,2154.23
  Top Layer w20: R28.1@1423.59,2140.72 1438.97,2156.1 1499.82,2156.1
LO1_G: C39.1 Q2.4 R28.2 | length 203.3
  Top Layer w16: Q2.4@1319.33,1959.68 1347.12,1959.68 C39.1@1349.85,1962.4
  Top Layer w20: v1(1425.13,2079.56) R28.2@1425.13,2099.18
  Signal Layer 2 w20: v1(1345.36,1962.26) 1345.36,2002.64 1422.28,2079.56 v1(1425.13,2079.56)
LO2: R32.1 U1.30 | length 122.2
  Top Layer w20: R32.1@1484.88,1987.44 1484.88,2026.33 1510.78,2052.23 1510.78,2067.81 1526.94,2083.96 1526.94,2085.02 1532.02,2090.09
LO2_G: C23.1 Q3.4 R32.2 | length 91.9
  Top Layer w20: Q3.4@1435.06,1867.75 Q3.4@1435.06,1874.96 ; Q3.4@1435.06,1877.95 1435.06,1893.26 1455.01,1913.21 C23.1@1463.58,1913.21 ; C23.1@1471.26,1920.5 1482.88,1932.12 1482.88,1945.44 R32.2@1484.88,1947.44
MODE: J8.19 JP5.2 U1.7 | length 4781.8
  Top Layer w10: U1.7@1762.17,2213.28 v1@1783.04,2213.28
  Signal Layer 2 w10: J8.19@1149.03,1261.43 1149.03,1275.23 1162.7,1288.9 1162.7,1292.12 1219.45,1348.87 1868.92,1348.87 v1@1964.96,1444.91 ; v1@1783.04,2213.28 1781.13,2211.37 1781.13,2204.3 1760.52,2183.68 1760.52,2131.33 1782.82,2109.03 1782.82,2065.92 1794.75,2053.98 1811.9,2053.98 1815.35,2057.42 1839.17,2057.42 1913.42,1983.18 1913.42,1933.58 1943.47,1903.54 1943.47,1852.15 2016.8,1778.82 2016.8,1497.46 v1(1963.04,1443.71) ; v1(2256.29,1358.95) 2364.11,1466.77 2364.11,1684.3 2733.91,2054.1 2733.91,2863.59 2503,3094.5 2503,3399.84 JP5.2@2412.74,3490.11
  Signal Layer 4 w10: v1@1961.62,1441.58 2047,1526.96 2189.29,1526.96 2256.29,1459.96 v1(2256.29,1358.95)
  other v1: 1783.24,2213.98
NetC4_1: C4.1 D2.2 Q5.4 R34.1 | length 374.5
  Top Layer w10: Q5.4@621.54,1727.01 725.98,1727.01 731.96,1732.99 R34.1@731.96,1737.49 731.51,1737.94 731.51,1778.12 C4.1@731.06,1778.57 731.06,1809.26 785.69,1863.89 845.93,1863.89 859.35,1850.48 859.35,1834.38 D2.2@868.13,1825.6
NetC6_2: C6.2 D2.3 | length 61.1
  Top Layer w10: D2.3@830.72,1904.34 830.72,1906.35 839.5,1915.13 866.04,1915.13 878.88,1927.97 C6.2@878.88,1929.94
NetC15_2: C15.2 R7.1 U1.36 | length 69.2
  Top Layer w9: v1(1642.6,2022.06) 1642.6,2024.21 1657.84,2039.45 U1.36@1657.84,2069.58
  Bottom Layer w10: R7.1@1640.03,2008.9 1641.31,2010.19 1641.31,2020.78 v1(1642.6,2022.06) v1@1643.73,2022.06
NetC16_1: C16.1 R9.1 U1.18 | length 48.6
  Top Layer w10: C16.1@1591.32,2349.76 1592.25,2349.76 1595.13,2346.88 1595.13,2310.21 1598.71,2306.63 U1.18@1598.71,2304.74
  other v1: 1590.9,2347.51
NetC18_1: C18.1 R52.1 | length 9.1
  Top Layer w10: R52.1@1701.87,2381.82 1710.68,2381.82 C18.1@1710.87,2381.62
NetC30_1: C30.1 R23.1 | length 92.6
  Bottom Layer w10: C30.1@1285.54,2085.03 C30.1@1285.54,2089.95 ; R23.1@1313.21,2128.72 1333.8,2149.31 R23.1@1342.15,2149.31
  Bottom Layer w16: C30.1@1285.54,2089.95 1313.21,2117.62 R23.1@1313.21,2128.72
NetC32_2: C32.2 R26.1 | length 80.6
  Bottom Layer w30: C32.2@1369.78,1740.81 1374.39,1736.2 1374.39,1719.51 1375.36,1718.55 1375.36,1677.46 R26.1@1385.95,1666.87
NetC36_1: C36.1 R29.1 | length 33.8
  Top Layer w10: R29.1@1813.82,2383.45 C36.1@1847.6,2383.45
NetJ7_3: J7.3 R16.1 | length 662.9
  Signal Layer 2 w10: v1(1903.39,2450.05) 1918.51,2465.17 1918.51,2737.26 1905.28,2750.49 1905.28,2867.9 1905.28,2917.67 J7.3@1949.03,2961.43
  Bottom Layer w10: R16.1@1832.51,2366.77 1837.51,2371.77 1837.51,2382.75 1842.51,2387.75 1857.9,2387.75 1901.84,2431.7 1901.84,2448.5 v1(1903.39,2450.05)
NetJ7_6: J7.6 R55.2 | length 668.3
  Signal Layer 2 w10: J7.6@1849.03,2861.43 1843.21,2855.61 1843.21,2822.88 1793.75,2773.42 1793.75,2609.52 1872.65,2530.62 1872.65,2481.82 1858.01,2467.18 1858.01,2452.61 v1(1856.09,2450.7)
  Bottom Layer w10: R55.2@1701.34,2375.26 1706.34,2380.26 1706.34,2395.79 1742.25,2431.69 1837.09,2431.69 v1(1856.09,2450.7)
NetJ7_16: J7.16 R42.2 | length 81.8
  Bottom Layer w10: R42.2@1349.03,2779.58 J7.16@1349.03,2861.43
NetJ7_17: J7.17 R33.1 | length 2983
  Signal Layer 2 w10: v1(2191.78,2467.08) 2193.69,2465.17 2204.53,2465.17 2349.99,2319.71 2349.99,2152.29 v1@2336.15,2138.46
  Signal Layer 4 w10: J7.17@1238.26,2957.7 1188.26,3007.7 1104,3007.7 1039.8,2943.51 1039.8,2739.64 1105.82,2673.61 1299.55,2673.61 1337.59,2711.66 1759.55,2711.66 1801.49,2669.71 1996.34,2669.71 2189.86,2476.19 2189.86,2469 v1(2191.78,2467.08) v1@2191.78,2460.64 ; v1(1863.75,1995.56) 1865.66,1997.47 v1@1872.73,1997.47 ; v1@1872.76,1997.49 2170.38,1997.49 2236.67,1931.21 2353.39,1931.21 2399.41,1977.23 2399.41,2061.25 2338.07,2122.59 2338.07,2141.55 v1(2336.15,2143.46)
  Bottom Layer w10: R33.1@1852.29,2035.21 1855.53,2031.97 1855.53,2003.67 v1@1863.88,1995.32
NetJ7_19: J7.19 R43.1 | length 2814.5
  Signal Layer 2 w10: v1(2220.59,2481.67) 2222.5,2479.75 2222.5,2469.82 2365.99,2326.33 v1(2365.99,2132.55) v1@2365.99,2127.55
  Signal Layer 4 w10: J7.19@1138.26,2957.7 1086.22,2957.7 1063.98,2935.46 1063.98,2749.06 1119.34,2693.69 1291.05,2693.69 1329.22,2731.86 1768.56,2731.86 1809.57,2690.86 2005.72,2690.86 2210.07,2486.51 2213.04,2486.51 2217.88,2481.67 v1(2220.59,2481.67) ; v1@1859.62,1960.3 1879.75,1980.43 2160.61,1980.43 2230.46,1910.58 2361.26,1910.58 2420.11,1969.43 2420.11,2071.36 2367.9,2123.56 2367.9,2130.63 v1(2365.99,2132.55)
  Bottom Layer w10: R43.1@1846.48,1943.31 1846.48,1950.81 1854.05,1958.38 1856.77,1958.38 v1(1858.68,1960.3)
NetJ7_20: J7.20 R41.2 | length 84.5
  Bottom Layer w10: R41.2@1149.03,2776.96 J7.20@1149.03,2861.43
NetJP2_2: JP2.2 R8.1 R12.2 | length 255.1
  Signal Layer 4 w10: v1(1491.12,2343.79) 1489.21,2345.7 1486.18,2345.7 1477.24,2354.64 1477.24,2465.65 1499.18,2487.59 1499.18,2499.51 1504.78,2499.51 JP2.2@1504.78,2505.1
  Bottom Layer w10: JP2.2@1504.78,2505.1 1504.78,2434.3 R8.1@1505.36,2433.72
NetL1_1: L1.1 R4.2 R18.2 | length 521.4
  Top Layer w10: R18.2@1364.07,2302.85 1384.2,2282.73 1384.2,2246.71 1394.48,2236.43 1395.89,2236.43 1400.89,2231.43 v1(1403.59,2231.43)
  Top Layer w45: L1.1@1372.44,1824.8 1372.44,1864.25 1391.59,1883.4 R4.2@1391.59,1938.4
  Signal Layer 4 w10: v1(1403.59,2231.43) 1430.38,2204.65 1430.38,2152.87 1474.24,2109.01 1474.24,2022.63 1436.58,1984.97 1436.58,1979.23 1435.31,1977.96 1435.31,1969.87 v1(1433.4,1967.96)
NetQ5_5: Q5.5 Q5.6 Q5.7 Q5.8 Q5.9@546.54,1880.56 R1.1 R5.2 TP1.1 | length 1502.7
  Top Layer w10: Q5.9@594.54,1851.67 Q5.9@624.94,1821.27
  Signal Layer 4 w10: v1(587.67,2024.92) 585.76,2026.84 585.76,2037.1 577.63,2045.23 489.74,2045.23 458.52,2076.45 458.52,2169.86 757.4,2468.75 1289.18,2468.75 1320.57,2437.35 1415.06,2437.35 1426.89,2425.51 1426.89,2425.27 1431.89,2420.27 v1(1431.89,2417.56)
  Bottom Layer w10: v1(1431.89,2417.56) 1452.55,2396.9 1452.55,2362.47 1444.42,2354.33 1436.55,2354.33 1432.2,2349.98 R5.2@1432.2,2349.49
  other v1: 560.65,1805.56 560.65,1826.67 545.14,2024.92 566.41,2024.92 608.93,2024.92 630.2,2024.92
  other v3: 680.05,1831.97 399.56,1833.44 349.5,1887.48 678.95,1945.44 560.65,1948.04 399.56,1950.93
NetR10_2: R10.2 U1.15 | length 21.3
  Top Layer w10: U1.15@1657.84,2297.93 v1@1657.84,2319.27
  other v1: 1658.48,2318.96
NetR27_2: R27.2 R41.1 R42.1 | length 1813.5
  Signal Layer 2 w10: v1(1246.8,2743.58) 1432.19,2743.58 v1(1553.92,2621.85) ; v1(1991.23,2154.15) 2008.79,2154.15 2027.61,2172.97 2035.17,2172.97 2093.48,2231.28 2174.18,2231.28 2208.43,2265.54 2208.43,2343.9 2166.55,2385.79 2081.45,2385.79 v1@2057.69,2409.55
  Signal Layer 4 w10: v1(1553.92,2621.85) 1599.51,2576.25 2012.51,2576.25 2057.67,2531.1 v1(2057.67,2409.57)
  Bottom Layer w10: R41.1@1205.98,2761.76 1205.98,2754.26 1215.45,2744.78 1245.59,2744.78 v1(1246.8,2743.58) 1276.73,2743.58 1282.59,2749.44 1282.59,2758.85 R42.1@1287.59,2763.85 ; R27.2@1851.47,2090.77 1853.76,2093.06 1930.14,2093.06 v1(1991.23,2154.15)
nFLT: J8.6 R25.1 R54.1 U1.11 | length 1960.6
  Signal Layer 2 w10: v1(2030.36,1902.61) 2063,1902.61 2157.27,1808.34 v1(2157.27,1484.36)
  Signal Layer 4 w10: J8.6@1849.03,1161.43 1921.76,1088.7 2105.34,1088.7 2158.58,1141.94 2158.58,1483.05 v1(2157.27,1484.36) ; v1(1915.37,2262.76) 1915.37,2188.45 1940.91,2162.91 1940.91,2144.34 1995.14,2090.11 2060.32,2090.11 2060.78,2090.57 2067.85,2090.57 v1(2069.76,2092.48)
  Bottom Layer w10: v1(1741.14,2296.29) 1741.14,2258.74 1755.52,2244.36 1782.2,2244.36 1782.24,2244.31 1782.24,2243.46 R25.1@1782.24,2238.96 ; R25.1@1782.26,2237.81 1784.76,2235.31 1790.38,2235.31 1790.71,2234.98 1791.93,2234.98 1809.27,2217.64 1897.84,2217.64 1915.37,2235.17 v1(1915.37,2262.76) ; R25.1@1784.74,2235.33 R25.1@1784.74,2236.46 ; v1(2030.36,1902.61) 2030.36,2055.99 2035.36,2060.99 R54.1@2044.54,2060.99 ; R54.1@2041.62,2060.99 2049.12,2060.99 2054.12,2065.99 2067.85,2079.72 2067.85,2090.57 v1(2069.76,2092.48)
nRST: R35.1 TP11.1 U1.38 | length 636.1
  Top Layer w9: U1.38@1697.21,2069.58 1697.63,2069.16 1697.63,2058.34 v1@1715.46,2040.51
  Signal Layer 4 w10: TP11.1@1473.44,1543.96 1586.78,1657.3 1586.78,1691.05 1682.67,1786.94 1682.67,1963.34 1704.93,1985.6 1704.93,2029.44 1715.59,2040.09 v1(1715.59,2040.51)
  Bottom Layer w10: v1@1713.75,2042.3 1715.45,2040.6 v1@1715.63,2040.6
Q4_D: C3.2 C5.2 C8.2 C10.2 C13.2 C21.2 C24.2 J4.3 JP2.1 Q4.5-6-7-8 R3.1 R8.2 R9.2 R14.2 TP6.1 | length 4449.9
  Top Layer w10: Q4.5-6-7-8@1685.14,1802 1685.14,1814 ; 1686.79,1813.33 1694.03,1813.33 ; C5.2@1795.47,1671.52 1795.47,1677.71 C5.2@1804.55,1686.79
  Top Layer w20: C8.2@2303.81,846.85 2316.52,846.85 2338,825.37 J4.3@2338,756.82 J4.3@2338,751.05
  Signal Layer 2 w10: v1@1363.23,2344.48 1362.36,2343.62 1362.36,2333.84 1332.27,2303.75 1224.66,2303.75 1170.18,2249.28 1170.18,1856.9 1310.47,1716.61 1513.72,1716.61 1608.4,1621.92 1826.1,1621.92 1859.18,1655 v1(1859.18,1657.71) 1873.91,1642.98 1873.91,1599.87 TP6.1@1726.13,1452.1 ; JP2.1@1405,2505 1409.43,2505 1504.93,2409.5 1469.66,2374.24 1469.66,2318.8 1530.32,2258.15 1530.32,2151.6 1594.05,2087.86 1651.01,2087.86 1694.59,2044.29 1694.59,1982.06 1683.7,1971.16 1683.7,1937.68 1700.61,1920.77 1700.61,1785.02 v1(1732.54,1753.08) ; 1502.58,2407.15 1581.44,2407.15 v1(1582.81,2405.79)
  Signal Layer 4 w10: v1(1732.54,1753.08) 1732.54,1621.11 1806.95,1546.7 1968.7,1546.7 2011.23,1589.23 2222.4,1589.23 2326.15,1485.48 2326.15,1309.8 2298.65,1282.3 2298.65,857.98 2300.94,855.69 2300.94,849.04 v1(2302.85,847.13)
  Bottom Layer w10: R8.2@1545.36,2433.72 1545.36,2430.62 1547.86,2428.12 1560.48,2428.12 v1(1582.81,2405.79) 1582.81,2404.71 1584.72,2402.8 1584.72,2385.01 R9.2@1587.91,2381.81
  other v1: 1364.28,2344.19
RT: R31.2 U1.12 | length 121.4
  Top Layer w10: U1.12@1716.9,2297.93 1716.9,2313.67 1723.17,2319.94 v1(1723.17,2322.65) 1724.84,2324.32 1753.62,2324.32 1767.73,2310.21 R31.2@1810.67,2310.21
SCL: J10.9 R33.2 R39.1 U1.6 | length 2918.4
  Top Layer w9: U1.6@1762.17,2193.6 1762.29,2193.48 1789.73,2193.48 1807.67,2175.54 1822.08,2175.54 v1(1823.44,2174.18) v1@1825.2,2172.42
  Signal Layer 4 w10: J10.9@1413,3452.5 J10.9@1415.71,3449.79 ; v1(1488.82,3436.74) 1514.11,3462.03 1566.53,3462.03 1808.76,3219.8 2071.77,3219.8 2259.22,3032.35 2259.22,2830.93 2399.89,2690.26 2399.89,2299.45 2135.28,2034.84 1964.68,2034.84 1881.64,2117.88 1881.64,2136.77 1849.52,2168.89 1830.65,2168.89 1830.65,2115.24 1816.03,2100.62 1799.06,2100.62 1783.41,2084.97 1783.41,2037.84 1810.98,2010.27 1819.28,2010.27 v1@1819.46,2010.08
  Signal Layer 4 w16: v1(1823.44,2174.18) v1@1827.68,2169.94
  Bottom Layer w9: v1(1488.82,3436.74) R39.1@1494.32,3442.24
  Bottom Layer w10: J10.9@1413,3452.87 1429.13,3436.74 v1(1488.82,3436.74) ; R33.2@1791.35,2035.21 1791.35,2027.71 1796.35,2022.71 1803.85,2022.71 1816.47,2010.08 v1@1819.46,2010.08
  other v1: 1819.34,2008.35
SDA: J10.10 R40.1 R43.2 U1.5 | length 3109.7
  Top Layer w10: U1.5@1768,2173.91 U1.5@1762.17,2173.91 1762.25,2173.83 1782.92,2173.83 v1@1783.11,2173.64
  Signal Layer 4 w10: v1(1548.82,3436.74) 1550.23,3435.34 1562.77,3435.34 1799.53,3198.57 2060.58,3198.57 2237.94,3021.21 2237.94,2820.59 2378.53,2680 2378.53,2307.93 2122.48,2051.88 1975.77,2051.88 1900.8,2126.85 1900.8,2145.4 1874.5,2171.7 1874.5,2203.12 1861.92,2215.71 1825.17,2215.71 1783.11,2173.64 1783.11,2170.94 1777.25,2165.07 1777.25,2150.19 1736.58,2109.52 1736.58,2080.2 1760.33,2056.45 1760.33,1992.25 1779.16,1973.42 1785.88,1973.42 v1@1787.79,1971.5
  Bottom Layer w9: J10.10@1413.82,3551.74 1365.07,3502.99 1365.07,3430.49 1393.82,3401.74 1513.82,3401.74 1535.82,3423.74 1535.82,3431.24 R40.1@1541.32,3436.74 ; v1(1548.82,3436.74) R40.1@1556.32,3436.74
  Bottom Layer w10: R43.2@1786.48,1943.31 1789.9,1946.73 1789.9,1970.69 v1(1791.81,1972.61)
  other v1: 1781.58,2172.64
SS/ATRK: C37.1 R27.1 TP13.1 U1.2 | length 324.6
  Top Layer w10: U1.2@1762.17,2114.86 1768.91,2114.86 1768.98,2114.78 1776.41,2114.78 1787.31,2103.88 1787.31,2090.93 v1@1797.51,2080.74
  Bottom Layer w10: v1(1806.51,2076.79) 1827.8,2098.07 1827.8,2136.05 1868.95,2177.2 1933.76,2177.2 TP13.1@1987.84,2231.28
